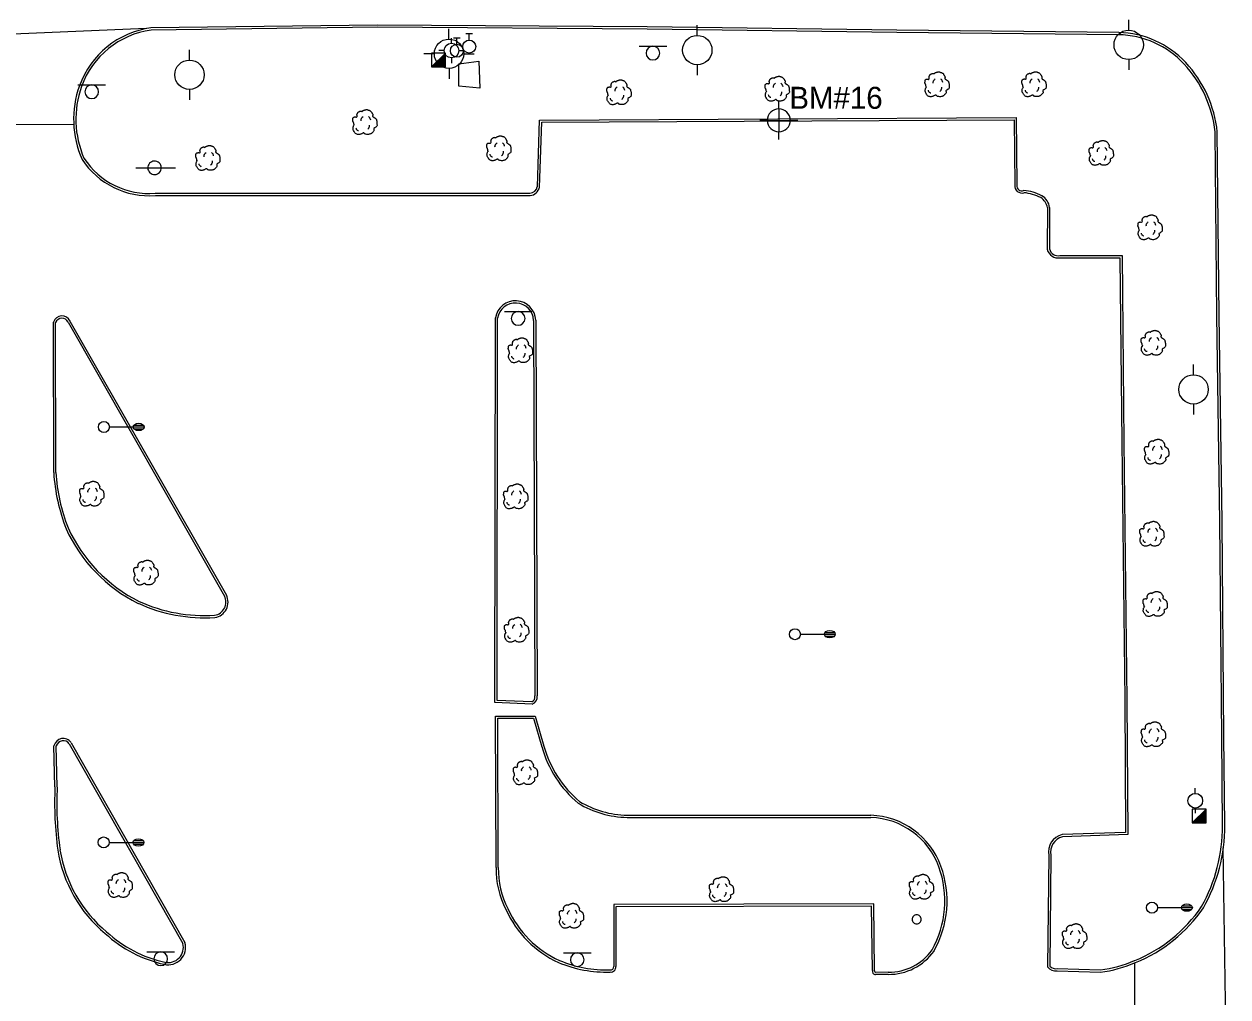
# Model space of a CAD drawing. Extents: x 2145380 to 2156929, y 139568 to 149130.
# Drawn here: x 2146129.5 to 2146457.5, y 142663 to 142928.2 of the extents above; entities that cross this region are included whole.
import ezdxf

# ---------------------------------------------------------------- set-up
doc = ezdxf.new("R2010")
doc.units = 0
for name, color, linetype in [('Default', 7, 'Continuous'), ('SURV_Benchmark', 7, 'Continuous'), ('SURV_Text', 7, 'Continuous'), ('TOPO_Asphalt', 7, 'Continuous'), ('TOPO_Concrete', 7, 'Continuous'), ('TOPO_Curb Back', 7, 'Continuous'), ('TOPO_Light Pole', 7, 'Continuous'), ('TOPO_Misc', 7, 'Continuous'), ('TOPO_Power Pole', 7, 'Continuous'), ('TOPO_Sign', 7, 'Continuous'), ('TOPO_Tree', 7, 'Continuous'), ('TOPO_Water Fire Hydrant', 7, 'Continuous'), ('TOPO_Water Valve', 7, 'Continuous')]:
    doc.layers.add(name, color=color, linetype=linetype)

# ---------------------------------------------------------------- blocks, each defined once
blk = doc.blocks.new('FIRHYD')
at = {"layer": 'TOPO_Water Fire Hydrant'}
for p, q in [((-0.02, 10.16), (-0.03, 17.34)), ((10.16, 0.02), (17.34, 0.03)), ((-10.16, -0.02), (-17.34, -0.03)), ((0.02, -10.16), (0.03, -17.34))]:
    blk.add_line(p, q, dxfattribs=at)
blk.add_circle((0, 0), 10.16, dxfattribs=at)
blk = doc.blocks.new('POWPOL')
at = {"layer": 'TOPO_Power Pole'}
for p, q in [((0, 10.16), (0, 17.34)), ((0, -10.16), (0, -17.34))]:
    blk.add_line(p, q, dxfattribs=at)
blk.add_circle((0, 0), 10.16, dxfattribs=at)
blk = doc.blocks.new('LP')
at = {"layer": 'TOPO_Light Pole'}
blk.add_line((3.81, 0), (20.32, 0), dxfattribs=at)
for points in [[(20.32, 0), (27.94, 0)], [(20.32, 0), (23.5, 0)], [(20.83, 1.27), (27.43, 1.27)], [(20.83, 1.27), (23.5, 1.27)], [(23.71, 1.27), (27.43, 1.27)], [(23.71, 0), (27.94, 0)], [(20.83, -1.27), (27.43, -1.27)], [(20.83, -1.27), (23.5, -1.27)], [(23.71, -1.27), (27.43, -1.27)]]:
    blk.add_lwpolyline(points, dxfattribs=at)
blk.add_circle((0, 0), 3.81, dxfattribs=at)
blk.add_ellipse((24.13, 0), major_axis=(3.81, 0), ratio=0.666667, dxfattribs=at)
blk = doc.blocks.new('POST')
at = {"layer": 'TOPO_Misc'}
for start, end in [(89.99996, 180.00004), (179.99996, 270.00004), (359.99996, 90.00004), (269.99996, 0.00004)]:
    blk.add_arc((-0.01, 0.03), 3.16, start, end, dxfattribs=at)
blk = doc.blocks.new('TREE')
at = {"layer": 'TOPO_Tree'}
for points in [[(-14.1, -0.4), (-14.2, 0.5), (-14.4, 1.4), (-14.6, 2.3), (-14.8, 3.2), (-15.5, 4), (-15.7, 4.9), (-15.8, 5.6), (-15.7, 6.3), (-15.7, 7), (-15.6, 7.9), (-15.7, 8.8), (-15.1, 9.7), (-14.6, 10.4), (-13.8, 10.5), (-13, 10.7), (-12.2, 11), (-11.1, 10), (-10.4, 10.7), (-9.4, 11.7), (-10.3, 13.3), (-9.8, 14.4), (-9.6, 15.1), (-9.3, 15.9), (-8.8, 16.5), (-8.2, 17.3), (-7.5, 17.7), (-6.7, 18.1), (-6.1, 18.4), (-5.6, 18.6), (-5.1, 18.7), (-4.5, 18.7), (-4, 18.5), (-3.5, 18.1)], [(-3.5, 17.6), (-3.1, 18.3), (-2.6, 18.8), (-1.9, 19.2), (-1, 19.7), (-0.2, 20), (0.7, 20.2), (1.6, 20.5), (2.5, 20.8), (3.4, 20.8), (4.1, 20.7), (4.8, 20.5), (5.5, 20.2), (6.4, 19.9), (7.3, 19.7), (8.2, 19.2), (9.4, 18.4), (10, 17.2), (10.8, 16), (11.2, 15.3), (11.6, 14.6), (11.9, 13.9), (12.2, 13.1), (11.4, 12), (11.9, 11.2), (12, 11), (12.2, 10.9), (12.4, 10.7), (12.9, 10.4), (13.5, 10), (14, 9.7), (14.7, 9.2), (15.4, 8.7), (16.1, 8.1), (16.7, 7.5), (16.9, 6.7), (17.1, 6), (17.6, 4.4), (17.7, 2.8), (17.7, 1.2), (17.7, -0.2), (17.8, -2.2), (16.6, -3), (15.5, -3.8), (14.3, -4.6), (13.2, -5.3)], [(13.2, -5.3), (13.3, -5.8), (13.4, -6.3), (13.4, -6.7), (13.8, -8.5), (12.2, -10), (10.8, -11.5), (10, -12.3), (9.1, -12.8), (8.2, -13.1), (6, -13.8), (3.3, -13.6), (1.3, -13.1), (0.5, -12.9), (-0.1, -11.4), (-0.8, -11.5), (-2, -11.6), (-3.3, -12.8), (-4.5, -13.1), (-6.1, -13.5), (-7.8, -14), (-9.3, -13.6), (-11.4, -13.1), (-12.8, -11.4), (-14.1, -9.4), (-15.3, -7.3), (-15.6, -5.1), (-15.1, -3), (-14.9, -1.9), (-13.9, -0.8), (-13.5, 0.1)], [(-4.2, 5.1), (-4.5, 6.1), (-4.3, 7.2), (-3.8, 8.2), (-3.3, 9.3), (-2.7, 10.3), (-1.6, 11)], [(5.9, 11.2), (6.5, 10.7), (7, 10.2), (7.4, 9.5), (7.9, 8.6), (8.3, 7.6), (8.5, 6.6)], [(-11.4, -4.5), (-11.5, -5.4), (-11, -6.3), (-10.1, -7.2), (-9.3, -8), (-8.5, -8.3), (-7.7, -8.1)], [(4.8, -6.3), (5.7, -5.7), (6.3, -4.9), (6.8, -3.9), (7.4, -2.8), (7.6, -1.7), (7.5, -0.6)]]:
    blk.add_open_spline(points, degree=3, dxfattribs=at)
blk = doc.blocks.new('WATVAL')
at = {"layer": 'Default'}
for p, q in [((-2.25, 9), (2.25, 9)), ((0, 4.5), (0, 9))]:
    blk.add_line(p, q, dxfattribs=at)
blk.add_circle((0, 0), 4.5, dxfattribs=at)
blk = doc.blocks.new('BM')
at = {"layer": 'SURV_Benchmark'}
for p, q in [((0, 2.49), (0, 4.15)), ((-2.49, 0), (-4.16, 0)), ((4.16, 0), (2.49, 0)), ((0, -4.16), (0, -2.49))]:
    blk.add_line(p, q, dxfattribs=at)
for points in [[(-2.5, 0), (-2.49, 0), (0, 0), (0, -2.49), (0, -2.49)], [(-2.5, 0), (-2.49, 0), (0, 0), (0, -2.49), (0, -2.49)], [(0, 2.49), (0, 2.49), (0, 0), (2.49, 0), (2.49, 0), (2.49, 0)], [(0, 2.49), (0, 2.49), (0, 0), (2.49, 0), (2.49, 0), (2.49, 0), (2.49, 0)]]:
    blk.add_lwpolyline(points, dxfattribs=at)
for start, end in [(90.0638, 180.0068), (0.0638, 90.0068), (0.0638, 90.0068), (180.0638, 270.0068), (180.0638, 270.0068), (269.9472, 359.9927)]:
    blk.add_arc((0, 0), 2.5, start, end, dxfattribs=at)

msp = doc.modelspace()

# ---------------------------------------------------------------- linework, layer by layer
at = {"layer": 'TOPO_Asphalt'}
for p, q in [((2146162.81, 142926.9), (2146088.05, 142923.82)), ((2146457.51, 142617.19), (2146456.26, 142703.58)), ((2146432.04, 142672.21), (2146432.02, 142640.82))]:
    msp.add_line(p, q, dxfattribs=at)
msp.add_lwpolyline([(2146143.08, 142900.75), (2146109.53, 142900.6), (2146108.01, 142840.92)], dxfattribs=at)
at = {"layer": 'TOPO_Concrete'}
msp.add_lwpolyline([(2146247.93, 142917.29), (2146253.44, 142918.08), (2146253.72, 142910.71), (2146248, 142911.27), (2146247.93, 142917.29)], dxfattribs=at)
at = {"layer": 'TOPO_Curb Back'}
for p, q in [((2146225.83, 142927.89), (2146164.1, 142927.11)), ((2146299.3, 142927.39), (2146225.83, 142927.89)), ((2146225.83, 142927.29), (2146164.14, 142926.51)), ((2146299.3, 142926.79), (2146225.83, 142927.29)), ((2146367.28, 142926.46), (2146299.3, 142927.39)), ((2146367.27, 142925.86), (2146299.3, 142926.79)), ((2146427.74, 142925.26), (2146367.27, 142925.86)), ((2146427.75, 142925.86), (2146367.28, 142926.46)), ((2146269.36, 142883.77), (2146269.99, 142901.99)), ((2146269.99, 142901.99), (2146399.83, 142902.69)), ((2146270.57, 142901.4), (2146399.24, 142902.08)), ((2146399.24, 142902.08), (2146399.44, 142884.25)), ((2146399.83, 142902.69), (2146400.04, 142884.22)), ((2146269.96, 142883.7), (2146270.57, 142901.4)), ((2146454.5, 142848.67), (2146454.02, 142898.73)), ((2146455.1, 142848.67), (2146454.62, 142898.77)), ((2146165.27, 142882.03), (2146218.21, 142882.02)), ((2146218.21, 142882.02), (2146267.35, 142882.02)), ((2146165.29, 142881.43), (2146218.21, 142881.42)), ((2146218.21, 142881.42), (2146267.37, 142881.42)), ((2146408.32, 142878.12), (2146408.3, 142866.77)), ((2146408.92, 142878.16), (2146408.9, 142866.84)), ((2146411.75, 142865.07), (2146428.68, 142865.06)), ((2146411.81, 142864.47), (2146428.09, 142864.46)), ((2146428.09, 142864.46), (2146428.59, 142814.22)), ((2146428.68, 142865.06), (2146429.19, 142814.23)), ((2146257.79, 142743.2), (2146257.95, 142848.04)), ((2146258.39, 142743.78), (2146258.55, 142847.99)), ((2146268.31, 142847.39), (2146268.71, 142745.03)), ((2146268.91, 142847.41), (2146269.31, 142745.08)), ((2146455.34, 142792.48), (2146454.5, 142848.67)), ((2146455.94, 142792.48), (2146455.1, 142848.67)), ((2146428.59, 142814.22), (2146429.38, 142743.88)), ((2146429.19, 142814.23), (2146429.98, 142743.88)), ((2146455.84, 142733.93), (2146455.34, 142792.48)), ((2146456.44, 142733.93), (2146455.94, 142792.48)), ((2146267.92, 142742.79), (2146257.79, 142743.2)), ((2146267.82, 142743.4), (2146258.39, 142743.78)), ((2146429.38, 142743.88), (2146429.61, 142707.8)), ((2146429.98, 142743.88), (2146430.22, 142707.22)), ((2146257.96, 142739.51), (2146268.78, 142739.52)), ((2146258.11, 142698.23), (2146257.96, 142739.51)), ((2146258.56, 142738.91), (2146268.33, 142738.92)), ((2146258.71, 142698.23), (2146258.56, 142738.91)), ((2146268.33, 142738.92), (2146270.58, 142731.18)), ((2146268.78, 142739.52), (2146271.16, 142731.35)), ((2146456.04, 142709.68), (2146455.84, 142733.93)), ((2146456.64, 142709.68), (2146456.44, 142733.93)), ((2146293.83, 142711.89), (2146360.25, 142711.88)), ((2146293.84, 142712.49), (2146360.26, 142712.48)), ((2146429.61, 142707.8), (2146412.34, 142707.21)), ((2146430.22, 142707.22), (2146412.42, 142706.62)), ((2146409.29, 142701.6), (2146408.99, 142671.35)), ((2146408.69, 142701.54), (2146408.39, 142671.13)), ((2146361, 142688.31), (2146290.16, 142688.14)), ((2146290.16, 142688.14), (2146290.16, 142671.25)), ((2146360.41, 142687.7), (2146290.76, 142687.54)), ((2146290.76, 142687.54), (2146290.76, 142671.29)), ((2146360.66, 142670.18), (2146360.41, 142687.7)), ((2146361.26, 142670.1), (2146361, 142688.31)), ((2146432.11, 142672.89), (2146432.11, 142672.89)), ((2146432.35, 142672.34), (2146432.34, 142672.33)), ((2146364.97, 142669.11), (2146361.46, 142669.04)), ((2146364.96, 142669.71), (2146361.5, 142669.64)), ((2146410.97, 142670.68), (2146422.76, 142670.31)), ((2146411.01, 142670.08), (2146422.78, 142669.71))]:
    msp.add_line(p, q, dxfattribs=at)
for points in [[(2146137.59, 142805.89), (2146137.52, 142846.93)], [(2146138.19, 142805.91), (2146138.12, 142846.82)], [(2146141.51, 142846.87), (2146184.11, 142772.21)], [(2146142.03, 142847.16), (2146184.63, 142772.5)], [(2146137.94, 142720.19), (2146137.67, 142731.44)], [(2146138.54, 142720.19), (2146138.27, 142731.37)], [(2146141.84, 142731.97), (2146172.77, 142677.53)], [(2146142.36, 142732.27), (2146173.33, 142677.76)]]:
    msp.add_lwpolyline(points, dxfattribs=at)
for centre, radius, start, end in [((2146167.36, 142903.14), 24.19, 97.7413, 160.1992), ((2146167.36, 142903.14), 23.59, 97.8302, 160.1944), ((2146427.24, 142900.29), 24.97, 42.7977, 88.8556), ((2146427.24, 142900.29), 25.57, 42.7984, 88.8624), ((2146421.83, 142895.24), 32.38, 6.1969, 42.8502), ((2146421.83, 142895.24), 32.98, 6.1452, 42.8497), ((2146170.47, 142902.21), 27.44, 160.5719, 203.4978), ((2146170.47, 142902.21), 26.84, 160.576, 203.3896), ((2146163.6, 142903.21), 21.84, 213.1349, 274.4329), ((2146163.6, 142903.21), 21.24, 213.2712, 274.4953), ((2146267.16, 142884.27), 2.25, 274.7408, 347.3117), ((2146267.16, 142884.27), 2.85, 274.2133, 348.5068), ((2146401.38, 142884.05), 1.95, 174.0436, 286.0102), ((2146401.38, 142884.05), 1.35, 172.714, 290.3745), ((2146400.65, 142869.2), 13.64, 63.1135, 84.9299), ((2146400.65, 142869.2), 13.04, 63.224, 84.3976), ((2146404.45, 142877.51), 3.92, 8.8678, 58.079), ((2146404.45, 142877.51), 4.52, 8.2484, 58.4292), ((2146411.26, 142867.46), 3.05, 193.1332, 280.2874), ((2146411.26, 142867.46), 2.45, 194.6785, 281.4858), ((2146263.4, 142847.2), 5.52, 2.1523, 171.1976), ((2146263.4, 142847.2), 4.92, 2.2667, 170.68), ((2146139.83, 142846.16), 2.43, 23.7339, 161.5912), ((2146139.83, 142846.16), 1.83, 23.7339, 158.7359), ((2146188.23, 142809.04), 50.74, 183.5572, 201.3357), ((2146188.23, 142809.04), 50.14, 183.5778, 201.3163), ((2146179.58, 142808.23), 42.46, 204.5635, 243.453), ((2146179.58, 142808.23), 41.86, 204.5867, 243.4387), ((2146178.68, 142809.79), 42.87, 245.4541, 273.6945), ((2146180.89, 142770.57), 3.61, 278.8125, 26.9815), ((2146180.89, 142770.57), 4.21, 278.435, 27.1831), ((2146178.68, 142809.79), 43.47, 245.4402, 273.7286), ((2146267.27, 142744.75), 1.46, 292.2463, 10.8513), ((2146267.27, 142744.75), 2.06, 288.3246, 9.1709), ((2146140.2, 142730.8), 2.61, 34.8965, 165.757), ((2146140.2, 142730.8), 2.01, 34.8965, 163.5645), ((2146299.94, 142739.2), 30.43, 195.2671, 230.3619), ((2146299.94, 142739.2), 29.83, 195.2577, 230.2775), ((2146231.19, 142715.73), 93.35, 177.2624, 187.8661), ((2146231.19, 142715.73), 92.75, 177.2491, 187.8623), ((2146294.35, 142738.54), 26.65, 238.7358, 268.877), ((2146294.35, 142738.54), 26.05, 238.8323, 268.8643), ((2146359.5, 142691.38), 20.51, 20.0023, 87.8949), ((2146359.5, 142691.38), 21.11, 19.9996, 87.9248), ((2146411.66, 142709.38), 44.38, 330.5848, 0.3866), ((2146411.66, 142709.38), 44.98, 330.5522, 0.3872), ((2146413.49, 142702.47), 4.89, 103.6351, 190.8962), ((2146413.49, 142702.47), 4.29, 104.4303, 191.6756), ((2146175.38, 142708.78), 37.13, 189.0179, 230.2036), ((2146175.38, 142708.78), 36.53, 189.0273, 230.2258), ((2146353.05, 142689.13), 27.34, 330.8183, 19.8144), ((2146353.05, 142689.13), 27.94, 330.7496, 19.8164), ((2146282.25, 142697.88), 24.14, 179.1724, 207.392), ((2146282.25, 142697.88), 23.54, 179.1592, 207.434), ((2146286.98, 142698.48), 28.67, 204.0922, 245.5969), ((2146286.98, 142698.48), 28.07, 204.0569, 245.5847), ((2146416.88, 142710.38), 40.47, 292.1051, 325.7038), ((2146416.88, 142710.38), 41.07, 292.1051, 325.7395), ((2146175.4, 142706.2), 35.2, 227.501, 257.3818), ((2146175.4, 142706.2), 34.6, 227.4775, 257.3876), ((2146168.79, 142676.46), 4.73, 256.7376, 16.0738), ((2146168.79, 142676.46), 4.13, 256.6921, 15.1184), ((2146365.09, 142684.27), 14.56, 269.5166, 324.3891), ((2146365.09, 142684.27), 15.16, 269.549, 324.517), ((2146287.95, 142702.17), 32.44, 246.7326, 272.2126), ((2146287.95, 142702.17), 31.84, 246.7433, 272.3189), ((2146418.43, 142704.24), 34.2, 277.2587, 293.5588), ((2146418.43, 142704.24), 34.8, 277.1802, 293.5588), ((2146289.39, 142671.13), 1.38, 262.3344, 6.8308), ((2146289.39, 142671.13), 0.779, 259.0402, 9.0954), ((2146361.58, 142669.98), 0.942, 167.5433, 262.6553), ((2146361.58, 142669.98), 0.342, 158.7083, 257.0386), ((2146410.61, 142672.88), 2.83, 218.3121, 278.1156), ((2146410.61, 142672.88), 2.23, 223.4736, 279.3729)]:
    msp.add_arc(centre, radius, start, end, dxfattribs=at)
at = {"layer": 'TOPO_Misc'}
for p, q in [((2146240.56, 142916.46), (2146244.3, 142920.21)), ((2146242.22, 142918.13), (2146244.3, 142918.13)), ((2146242.4, 142918.31), (2146244.3, 142918.31)), ((2146242.58, 142918.49), (2146244.3, 142918.49)), ((2146242.77, 142918.68), (2146244.3, 142918.68)), ((2146242.96, 142918.87), (2146244.3, 142918.87)), ((2146243.15, 142919.06), (2146244.3, 142919.06)), ((2146243.33, 142919.24), (2146244.3, 142919.24)), ((2146243.52, 142919.43), (2146244.3, 142919.43)), ((2146243.71, 142919.62), (2146244.3, 142919.62)), ((2146243.89, 142919.81), (2146244.3, 142919.81)), ((2146244.09, 142920), (2146244.3, 142920)), ((2146244.27, 142920.18), (2146244.3, 142920.18)), ((2146240.72, 142916.63), (2146244.3, 142916.63)), ((2146240.91, 142916.82), (2146244.3, 142916.82)), ((2146241.09, 142917), (2146244.3, 142917)), ((2146241.28, 142917.19), (2146244.3, 142917.19)), ((2146241.46, 142917.37), (2146244.3, 142917.37)), ((2146241.65, 142917.56), (2146244.3, 142917.56)), ((2146241.84, 142917.76), (2146244.3, 142917.76)), ((2146242.03, 142917.94), (2146244.3, 142917.94)), ((2146447.81, 142710.4), (2146451.54, 142714.15)), ((2146448.9, 142711.5), (2146451.55, 142711.5)), ((2146449.09, 142711.69), (2146451.55, 142711.69)), ((2146449.27, 142711.88), (2146451.54, 142711.88)), ((2146449.46, 142712.07), (2146451.54, 142712.07)), ((2146449.65, 142712.25), (2146451.54, 142712.25)), ((2146449.83, 142712.43), (2146451.54, 142712.43)), ((2146450.02, 142712.62), (2146451.54, 142712.62)), ((2146450.2, 142712.81), (2146451.54, 142712.81)), ((2146450.39, 142713), (2146451.54, 142713)), ((2146450.58, 142713.18), (2146451.54, 142713.18)), ((2146450.77, 142713.37), (2146451.54, 142713.37)), ((2146450.96, 142713.56), (2146451.54, 142713.56)), ((2146451.14, 142713.74), (2146451.54, 142713.74)), ((2146451.33, 142713.94), (2146451.54, 142713.94)), ((2146451.51, 142714.12), (2146451.54, 142714.12)), ((2146447.96, 142710.57), (2146451.55, 142710.57)), ((2146448.15, 142710.76), (2146451.55, 142710.76)), ((2146448.33, 142710.94), (2146451.55, 142710.94)), ((2146448.53, 142711.13), (2146451.55, 142711.13)), ((2146448.71, 142711.31), (2146451.55, 142711.31))]:
    msp.add_line(p, q, dxfattribs=at)
for points in [[(2146244.3, 142916.47), (2146244.3, 142920.21), (2146240.55, 142920.21), (2146240.56, 142916.46), (2146244.3, 142916.47)], [(2146451.55, 142710.41), (2146451.54, 142714.15), (2146447.8, 142714.15), (2146447.81, 142710.4), (2146451.55, 142710.41)]]:
    msp.add_lwpolyline(points, dxfattribs=at)
at = {"layer": 'TOPO_Sign'}
for points in [[(2146297.11, 142922.09), (2146304.61, 142922.1)], [(2146300.86, 142922.09), (2146300.86, 142922.09)], [(2146298.99, 142920.23), (2146298.99, 142920.23)], [(2146300.86, 142918.36), (2146300.86, 142918.36)], [(2146302.73, 142920.23), (2146302.73, 142920.23)], [(2146144.19, 142911.56), (2146151.68, 142911.56)], [(2146147.94, 142911.55), (2146147.94, 142911.55)], [(2146146.07, 142909.69), (2146146.07, 142909.69)], [(2146149.81, 142909.69), (2146149.81, 142909.69)], [(2146147.94, 142907.82), (2146147.94, 142907.82)], [(2146159.93, 142888.94), (2146170.81, 142889)], [(2146260.38, 142849.8), (2146267.87, 142849.8)], [(2146264.13, 142849.8), (2146264.13, 142849.8)], [(2146262.26, 142847.93), (2146262.26, 142847.93)], [(2146264.13, 142846.06), (2146264.13, 142846.06)], [(2146266, 142847.93), (2146266, 142847.93)], [(2146163, 142675.23), (2146170.49, 142675.24)], [(2146164.88, 142673.37), (2146164.88, 142673.37)], [(2146166.75, 142675.23), (2146166.75, 142675.23)], [(2146168.62, 142673.37), (2146168.62, 142673.37)], [(2146276.49, 142674.99), (2146283.99, 142675)], [(2146278.37, 142673.12), (2146278.37, 142673.12)], [(2146280.24, 142674.99), (2146280.24, 142674.99)], [(2146282.11, 142673.12), (2146282.11, 142673.12)], [(2146166.75, 142671.5), (2146166.75, 142671.5)], [(2146280.24, 142671.26), (2146280.24, 142671.26)]]:
    msp.add_lwpolyline(points, dxfattribs=at)
for centre, radius, start, end in [((2146300.86, 142920.23), 1.87, 90, 180), ((2146300.86, 142920.23), 1.87, 360, 90), ((2146300.86, 142920.23), 1.87, 180, 270), ((2146300.86, 142920.23), 1.87, 270, 0), ((2146147.94, 142909.69), 1.87, 90, 180), ((2146147.94, 142909.69), 1.87, 360, 90), ((2146147.94, 142909.69), 1.87, 180, 270), ((2146147.94, 142909.69), 1.87, 270, 0), ((2146165.07, 142888.96), 1.84, 47.4196, 227.4196), ((2146165.07, 142888.96), 1.84, 227.4196, 47.4196), ((2146264.13, 142847.93), 1.87, 90, 180), ((2146264.13, 142847.93), 1.87, 360, 90), ((2146264.13, 142847.93), 1.87, 180, 270), ((2146264.13, 142847.93), 1.87, 270, 0), ((2146166.75, 142673.37), 1.87, 90, 180), ((2146166.75, 142673.37), 1.87, 180, 270), ((2146166.75, 142673.37), 1.87, 360, 90), ((2146166.75, 142673.37), 1.87, 270, 0), ((2146280.24, 142673.12), 1.87, 90, 180), ((2146280.24, 142673.12), 1.87, 180, 270), ((2146280.24, 142673.12), 1.87, 360, 90), ((2146280.24, 142673.12), 1.87, 270, 0)]:
    msp.add_arc(centre, radius, start, end, dxfattribs=at)

# ---------------------------------------------------------------- block references
at = {"layer": 'SURV_Benchmark', "xscale": 1.25, "yscale": 1.25}
msp.add_blockref('BM', (2146335.15, 142901.9), dxfattribs=at)
at = {"layer": 'TOPO_Light Pole', "xscale": 0.39370000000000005, "yscale": 0.3937000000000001}
for p in [(2146151.26, 142818.33), (2146339.54, 142761.84), (2146151.19, 142705.08), (2146436.82, 142687.3)]:
    msp.add_blockref('LP', p, dxfattribs=at)
at = {"layer": 'TOPO_Misc', "xscale": 0.39370000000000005, "yscale": 0.3937000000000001}
msp.add_blockref('POST', (2146372.71, 142684.08), dxfattribs=at)
at = {"layer": 'TOPO_Power Pole'}
for p, xscale, yscale in [((2146312.94, 142921.06), 0.39370000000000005, 0.3937000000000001), ((2146430.48, 142922.49), 0.39370000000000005, 0.3937000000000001), ((2146174.59, 142914.34), 0.39370000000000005, 0.3937000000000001), ((2146448.14, 142828.56), 0.39370000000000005, 0.3937000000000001), ((2146448.63, 142716.45), 0.19685000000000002, 0.19685000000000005)]:
    msp.add_blockref('POWPOL', p, dxfattribs=dict(at, xscale=xscale, yscale=yscale))
at = {"layer": 'TOPO_Tree', "xscale": 0.19685000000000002, "yscale": 0.19685000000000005}
for p in [(2146378.07, 142911.04), (2146404.48, 142911.06), (2146291.41, 142908.88), (2146334.53, 142909.84), (2146222.19, 142900.75), (2146179.41, 142890.98), (2146258.69, 142893.6), (2146422.81, 142892.36), (2146436.11, 142872.07), (2146264.55, 142838.55), (2146436.98, 142840.58), (2146437.9, 142810.91), (2146147.77, 142799.45), (2146263.28, 142798.73), (2146436.61, 142788.53), (2146162.53, 142777.95), (2146437.49, 142769.41), (2146263.52, 142762.36), (2146437.01, 142733.89), (2146265.93, 142723.52), (2146155.52, 142692.79), (2146319.34, 142691.65), (2146373.83, 142692.3), (2146278.46, 142684.4), (2146415.55, 142678.85)]:
    msp.add_blockref('TREE', p, dxfattribs=at)
at = {"layer": 'TOPO_Water Fire Hydrant'}
for p, xscale, yscale in [((2146245.3, 142920.05), 0.39370000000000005, 0.3937000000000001), ((2146245.97, 142920.93), 0.19685000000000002, 0.19685000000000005)]:
    msp.add_blockref('FIRHYD', p, dxfattribs=dict(at, xscale=xscale, yscale=yscale))
at = {"layer": 'TOPO_Water Valve', "xscale": 0.39370000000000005, "yscale": 0.3937000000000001}
for p in [(2146250.8, 142922), (2146247.45, 142920.89)]:
    msp.add_blockref('WATVAL', p, dxfattribs=at)

# ---------------------------------------------------------------- texts
at = {"layer": 'SURV_Text'}
msp.add_text('BM#16', height=6, dxfattribs=at).set_placement((2146338.02, 142905.05))

doc.saveas('drawing.dxf')
